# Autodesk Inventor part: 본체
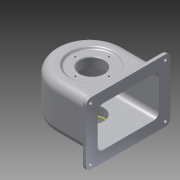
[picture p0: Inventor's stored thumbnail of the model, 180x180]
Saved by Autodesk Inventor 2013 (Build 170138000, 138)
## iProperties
Created: 2016-01
Part Number: 본체
Material: 알루미늄 6061
Document SubType Name: Modeling
Designer: dgall
Density: 2.71 g/cm^3
Mass: 809.754 g
Surface Area: 999.207 cm^2
Volume: 298.802 cm^3
Author: dgall
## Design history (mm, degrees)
sketch "스케치1"
  geometry: L1 (0, -57)-(64, -57); L2 (0, 57)-(64, 57); L3 (64, -57)-(64, 57); A1 r 57 centre (0, 0) between (0, 57) and (0, -57); 1 further point
  constraints: 6 end point, 2 point on circle, 2 tangent, 1 centre point, 1 coincident, 1 horizontal, 1 parallel, 1 perpendicular
  dimensions: "d4" = 114 diameter of A1; "d6" = 121 dimension on A1 L3
extrude "돌출1" new body sketch "스케치1" distance "d7" = 77; taper "d8" = 0 deg
feature "쉘1" dims "d9" = 6
sketch "스케치2"
  geometry: L1 (0, 0)-(64, 0) reference; L2 (0, -102)-(0, 0) reference; L3 (64, -102)-(0, -102) reference; A1 r 51 centre (64, -51) between (64, -102) and (64, 0) reference
extrude "돌출2" cut sketch "스케치2" distance "d10" = 1; taper "d11" = 0 deg
sketch "스케치3"
  geometry: L1 (64, 0)-(0, 0) reference; L2 (64, 102)-(64, 0) reference; L3 (0, 102)-(64, 102) reference; A1 r 51 centre (0, 51) between (0, 102) and (0, 0) reference
extrude "돌출3" cut sketch "스케치3" distance "d12" = 1; taper "d13" = 0 deg
sketch "스케치4"
  geometry: L1 (-64, 57)-(-64, -57) reference; L2 (-64, -57)-(0, -57) reference; L3 (-4, 24.205)-(-4, -25.457); L4 (0, 0)-(-23.424, 0); C1 r 31 at (-4, 0); A1 r 57 centre (0, 0) between (0, -57) and (0, 57) reference
  constraints: 4 end point, 2 perpendicular, 2 point on line, 1 centre point
  dimensions: "d131" = 60 distance between parallel lines of L1 L3; "d132" = 62 diameter of C1
extrude "돌출4" join sketch "스케치4" distance "d16" = 10; taper "d17" = 0 deg
sketch "스케치5"
  geometry: L1 (-4, 78.827)-(-4, -8.173); L2 (-64, 5)-(-64, 72) reference; L3 (-4, 58)-(16, 58); L4 (16, 58)-(16, 74); L5 (16, 58)-(24, 58); L6 (24, 58)-(35.747, 72); L7 (57, 77)-(0, 77) reference; L8 (-4, 74)-(30.899, 74); L9 (30.899, 74)-(33.416, 77); L10 (51, 72)-(0, 72) reference; L11 (35.747, 72)-(16, 72); L12 (-35, -10)-(27, -10) reference; 1 further point
  constraints: 16 end point, 6 point on line, 3 perpendicular, 2 parallel
  dimensions: "d26" = 60 distance between parallel lines of L2 L1; "d30" = 16 distance of L3.end L4.end; "d31" = 40 diameter of L4 L1; "d32" = 56 diameter of L5.end L1; "d34" = 3 distance between parallel lines of L7 L8; "d35" = 50 deg angle of L5 L6; "d36" = 5 distance between parallel lines of L6 L9; "d37" = 14 distance between parallel lines of L10 L5
revolve "회전1" sketch "스케치5" stored, may be unused: angle "d38" = 90 deg
sketch "스케치6"
  geometry: L1 (-24, 72)-(16, 72) reference; L2 (-4, 72)-(-4, 0); L3 (16, 72)-(16, 74); L4 (16, 74)-(30.899, 74); L5 (57, 77)-(0, 77) reference; L6 (35.747, 72)-(24, 58) reference; L7 (30.899, 74)-(33.416, 77); L8 (33.416, 77)-(-4, 77); L9 (-4, 77)-(-4, 72); L10 (16, 72)-(-4, 72); 1 further point
  constraints: 14 end point, 2 collinear, 2 parallel, 2 perpendicular, 2 point on line, 1 midpoint
  dimensions: "d39" = 3 distance between parallel lines of L5 L4; "d40" = 5 distance between parallel lines of L6 L7
revolve "회전2" sketch "스케치6" stored, may be unused: angle "d41" = 90 deg
sketch "스케치9"
  geometry: L1 (-72, 108)-(-5, 108) reference; L2 (-5, 108)-(-5, 6) reference; L3 (-5, 6)-(-72, 6) reference; L4 (-72, 6)-(-72, 108) reference; L5 (0, 114)-(0, 0) reference; L6 (0, 114)-(-77, 114) reference; L7 (-77, 0)-(-77, 114) reference; L8 (0, 0)-(-77, 0) reference; 1 further point
node "작업 평면4"
  node "작업 평면3"
sketch "스케치10"
  geometry: L1 (6, 5)-(108, 5) reference; L2 (108, 5)-(108, 72) reference; L3 (108, 72)-(6, 72) reference; L4 (6, 72)-(6, 5) reference; L5 (114, 77)-(114, 0) reference; L6 (114, 0)-(0, 0) reference; L7 (0, 0)-(0, 77) reference; L8 (0, 77)-(114, 77) reference; L9 (127, 90.5)-(-13, 90.5); L10 (-13, 90.5)-(-13, -13.5); L11 (-13, -13.5)-(127, -13.5); L12 (127, -13.5)-(127, 90.5); L13 (114, 38.5)-(0, 38.5); L14 (57, 77)-(57, 5); 1 further point
  constraints: 12 end point, 4 midpoint, 2 parallel, 1 horizontal, 1 perpendicular
  dimensions: "d54" = 104 distance of L11.end L9.start; "d56" = 140 distance of L9.start L9.end; "d57" = 70 distance between parallel lines of L12 L14; "d58" = 52 distance between parallel lines of L13 L9
extrude "돌출6" join sketch "스케치10" distance "d59" = 7; taper "d60" = 0 deg
fillet "모깎기1" dims "d61" = 14
fillet "모깎기3" dims "d63" = 9
fillet "모깎기4" dims "d64" = 3
fillet "모깎기5" dims "d68" = 1
fillet "모깎기6" dims "d69" = 8
fillet "모깎기7" dims "d70" = 3
sketch "스케치11"
  geometry: C1 r 2.5 at (-5.5, 5); C2 r 2.5 at (82.5, 5); C3 r 2.5 at (82.5, -119); C4 r 2.5 at (-5.5, -119); A1 r 5 centre (82.5, 5) between (87.5, 5) and (82.5, 10) reference; A2 r 5 centre (-5.5, 5) between (-5.5, 10) and (-10.5, 5) reference; A3 r 5 centre (-5.5, -119) between (-10.5, -119) and (-5.5, -124) reference; A4 r 5 centre (82.5, -119) between (82.5, -124) and (87.5, -119) reference; 1 further point
  constraints: 4 centre point, 4 coincident
  dimensions: "d71" = 5 diameter of C4; "d73" = 5 diameter of C1; "d74" = 5 diameter of C2; "d75" = 5 diameter of C3
extrude "돌출7" cut sketch "스케치11" stored distance "d76" = 7; taper "d77" = 0 deg
node "작업 평면5"
sketch "스케치12"
  geometry: L1 (-57, 63)-(57, 63) reference; L2 (-57, 14)-(-57, 63) reference; L3 (57, 14)-(-57, 14) reference; L4 (57, 14)-(57, 63) reference; L5 (-57, 38.5)-(57, 38.5); L6 (0, 63)-(0, 14); C1 r 6 at (0, 38.5); 1 further point
  constraints: 5 midpoint, 4 end point, 1 centre point
  dimensions: "d79" = 12 diameter of C1
extrude "돌출8" join sketch "스케치12" stored distance "d81" = 7; taper "d82" = 0 deg
sketch "스케치13"
  geometry: C1 r 6 at (0, 0) reference; 2 further points
  constraints: 1 coincident
hole "구멍1" sketch "스케치13" at (0, 0) diameter "d83" = 4.459; stored, may be unused: countersink angle "d87" = 90 deg, drill point angle "d89" = 118 deg; dims "d84" = 6, "d85" = 4, "d86" = 2, "d88" = 8
sketch "스케치15" dims "d102" = 56
  geometry: L1 (0, 0)-(-28, 0); C1 r 20 at (0, 0) reference; 2 further points
  constraints: 2 coincident, 2 end point, 1 horizontal, 1 horizontal alignment, 2 other
hole "구멍3" sketch "스케치15" at (-28, 0) diameter "d104" = 2.459; stored, may be unused: countersink angle "d108" = 90 deg, drill point angle "d110" = 118 deg; dims "d105" = 7, "d106" = 4, "d107" = 2, "d109" = 9
fillet "모깎기8" dims "d114" = 3
chamfer "모따기2" distance "d115" = 1; stored, may be unused: second distance "d116" = 2, angle "d117" = 45 deg
fillet "모깎기9" dims "d118" = 3
fillet "모깎기10" dims "d119" = 3
node "작업 평면6"
sketch "스케치16"
  geometry: L1 (100.528, 38.5)-(-99.777, 38.5); L2 (-34, 135.149)-(-34, -41.213); L3 (-64, -5.5)-(-64, 82.5) reference; L4 (0, 77)-(43, 77) reference; L5 (-30.398, 63.387)-(-30.398, 13.613); L6 (-30.398, 13.613)-(-37.602, 13.613); L7 (-37.602, 13.613)-(-37.602, 63.387); L8 (-37.602, 63.387)-(-30.398, 63.387); L9 (-34, 63.387)-(-34, 13.613); L10 (-30.398, 38.5)-(-37.602, 38.5); 1 further point
  constraints: 8 end point, 4 midpoint, 1 horizontal, 1 perpendicular, 2 other
  dimensions: "d121" = 30 distance between parallel lines of L3 L2; "d122" = 38.5 distance between parallel lines of L4 L1; "d123" = 0 distance between parallel lines of L2 L9; "d124" = 0 distance between parallel lines of L1 L10
feature "엠보싱1" sketch "스케치16" dims "d125" = 0.5, "d126" = 0
fillet "모깎기11" dims "d133" = 3
sketch "스케치18"
  geometry: C1 r 31 at (0, 0) reference; C2 r 19.496 at (0, 0); A1 r 51 centre (4, 0) between (4, -51) and (4, 51) reference; 1 further point
  constraints: 1 centre point, 1 coincident
extrude "돌출9" cut sketch "스케치18" distance "d140" = 15; taper "d141" = 0 deg
sketch "스케치19"
  geometry: C1 r 19.496 at (0, 0) reference; C2 r 31 at (0, 0) reference; 1 further point
node "솔리드1"
pattern_circular "원형 패턴2" dims angle "d112" = 360 deg
node "투영된 루프2"
node "절단 모서리 투영1"
other parameters: "d53" = -7, "d78" = -63, "d120" = 139
